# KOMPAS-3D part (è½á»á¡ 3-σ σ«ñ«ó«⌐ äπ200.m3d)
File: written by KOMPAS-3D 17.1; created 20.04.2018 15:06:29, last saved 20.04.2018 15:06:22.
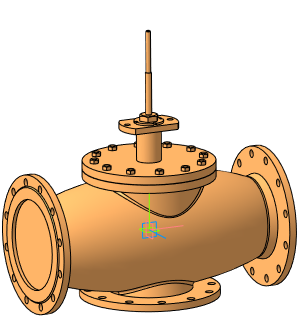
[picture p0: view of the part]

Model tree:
1. Операция без истории:2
